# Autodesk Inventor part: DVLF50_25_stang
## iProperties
Created: 2010-03
Part Number: DVLF50_25_stang
Document SubType Name: Modeling
Designer: TB
Mass: 170.559 g
Surface Area: 251.737 cm^2
Volume: 170.559 cm^3
Density: 1 g/cm^3
Author: TB
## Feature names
1. Revolution1
2. Fillet1
3. Revolution2
